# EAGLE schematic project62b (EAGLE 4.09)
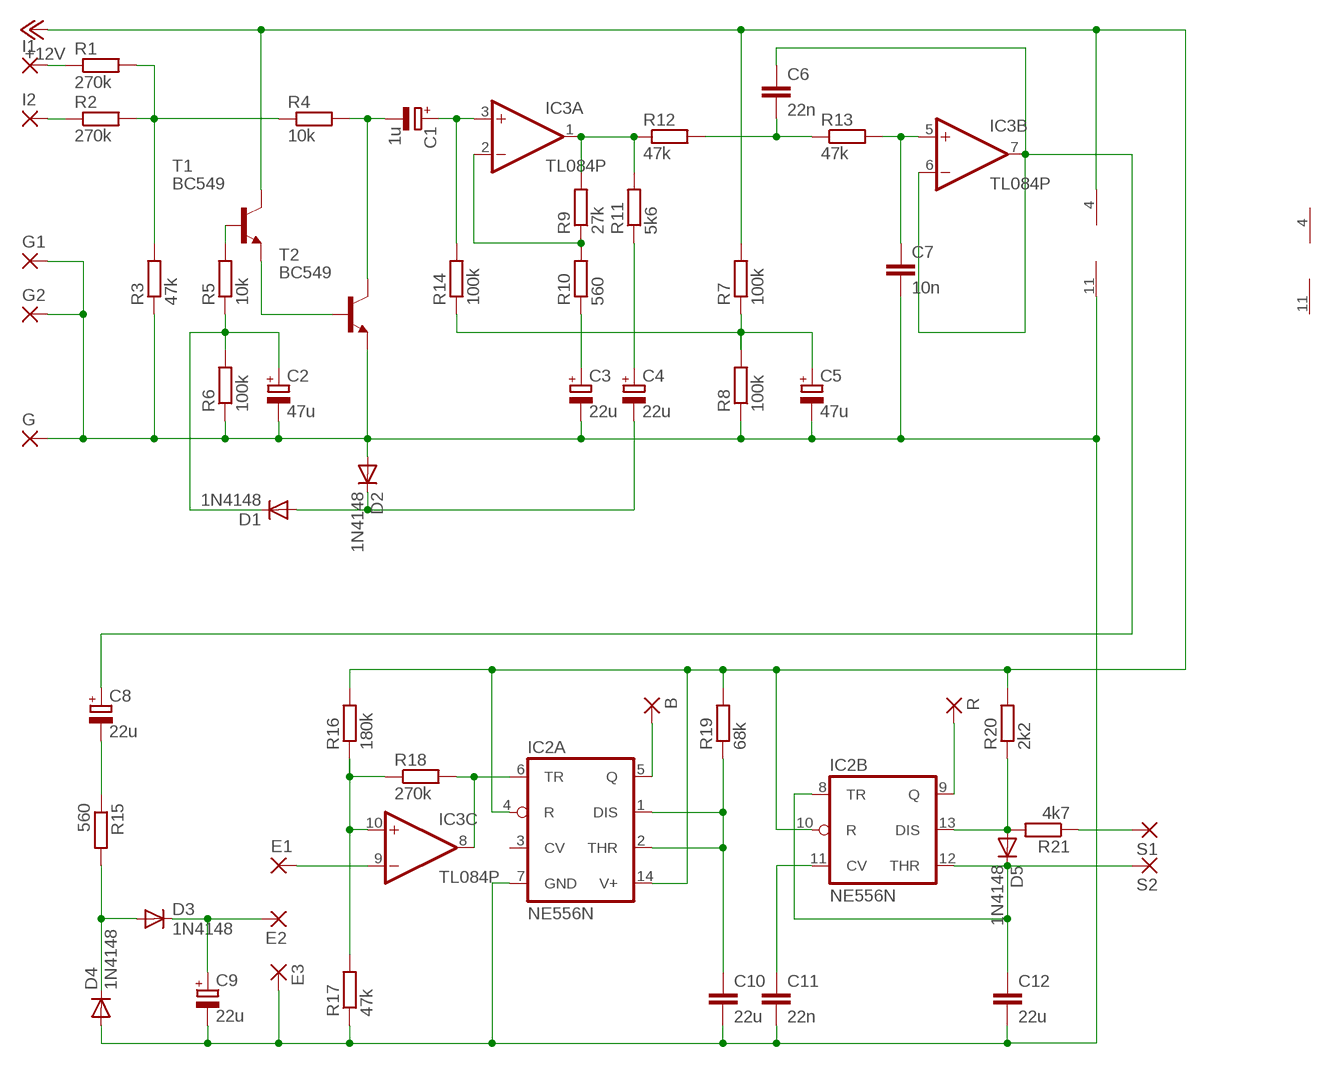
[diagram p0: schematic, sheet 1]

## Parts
B  2,54/0,8  [2,54/0,8]
C1  1u  CPOL-EUE5-6  [E5-6]
C2  47u  CPOL-EUE5-6  [E5-6]
C3  22u  CPOL-EUE5-6  [E5-6]
C4  22u  CPOL-EUE5-6  [E5-6]
C5  47u  CPOL-EUE5-6  [E5-6]
C6  22n  C-EU075-032X103  [C075-032X103]
C7  10n  C-EU075-032X103  [C075-032X103]
C8  22u  CPOL-EUE5-6  [E5-6]
C9  22u  CPOL-EUE5-6  [E5-6]
C10  22u  C-EU075-032X103  [C075-032X103]
C11  22n  C-EU075-032X103  [C075-032X103]
C12  22u  C-EU075-032X103  [C075-032X103]
D1  1N4148  [DO35-10]
D2  1N4148  [DO35-10]
D3  1N4148  [DO35-10]
D4  1N4148  [DO35-10]
D5  1N4148  [DO35-10]
E1  2,54/0,8  [2,54/0,8]
E2  2,54/0,8  [2,54/0,8]
E3  2,54/0,8  [2,54/0,8]
G  2,54/0,8  [2,54/0,8]
G1  2,54/0,8  [2,54/0,8]
G2  2,54/0,8  [2,54/0,8]
I1  2,54/0,8  [2,54/0,8]
I2  2,54/0,8  [2,54/0,8]
IC1  TL084_  [DIL14]
IC2  NE556N  [DIL14]
IC3  TL084P  [DIL14]
R  2,54/0,8  [2,54/0,8]
R1  270k  R-EU_0309/12  [0309/12]
R2  270k  R-EU_0309/12  [0309/12]
R3  47k  R-EU_0309/12  [0309/12]
R4  10k  R-EU_0309/12  [0309/12]
R5  10k  R-EU_0309/12  [0309/12]
R6  100k  R-EU_0309/12  [0309/12]
R7  100k  R-EU_0309/12  [0309/12]
R8  100k  R-EU_0309/12  [0309/12]
R9  27k  R-EU_0309/12  [0309/12]
R10  560  R-EU_0309/12  [0309/12]
R11  5k6  R-EU_0309/12  [0309/12]
R12  47k  R-EU_0309/12  [0309/12]
R13  47k  R-EU_0309/12  [0309/12]
R14  100k  R-EU_0309/12  [0309/12]
R15  560  R-EU_0309/12  [0309/12]
R16  180k  R-EU_0309/12  [0309/12]
R17  47k  R-EU_0309/12  [0309/12]
R18  270k  R-EU_0309/12  [0309/12]
R19  68k  R-EU_0309/12  [0309/12]
R20  2k2  R-EU_0309/12  [0309/12]
R21  4k7  R-EU_0309/12  [0309/12]
S1  2,54/0,8  [2,54/0,8]
S2  2,54/0,8  [2,54/0,8]
T1  BC549  BC547  [TO92]
T2  BC549  BC547  [TO92]

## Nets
+12V: IC1.4(P:V+) IC2.4(A:R) IC2.10(B:R) IC2.14(A:V+) R7.2 R16.2 R19.2 R20.2 T1.3(C)
GND_: C2.- C3.- C5.- C7.2 C9.- C10.2 C11.2 C12.2 D2.A D4.A E3.1(P) G1.1(P) G2.1(P) G.1(P) IC1.11(P:V-) IC2.7(A:GND) R3.1 R6.1 R8.1 R17.1 T2.1(E)
N$2: B.1(P) IC2.5(A:Q)
N$3: C6.1 C8.+ IC3.6(B:-IN) IC3.7(B:OUT)
N$4: R1.2 R2.2 R3.2 R4.1
N$5: T1.1(E) T2.2(B)
N$6: C1.- R4.2 T2.3(C)
N$7: C1.+ IC3.3(A:+IN) R14.2
N$8: I1.1(P) R1.1
N$9: R21.1 S1.1(P)
N$10: R5.2 T1.2(B)
N$11: C8.- R15.1
N$12: I2.1(P) R2.1
N$13: C5.+ R7.1 R8.2 R14.1
N$14: C6.2 R12.2 R13.1
N$15: D3.A D4.C R15.2
N$16: C7.1 IC3.5(B:+IN) R13.2
N$17: C4.- D1.A D2.C
N$18: IC3.1(A:OUT) R9.2 R11.2 R12.1
N$19: IC3.2(A:-IN) R9.1 R10.2
N$20: C3.+ R10.1
N$22: C4.+ R11.1
N$23: C9.+ D3.C E2.1(P)
N$24: D5.A IC2.13(B:DIS) R20.1 R21.2
N$25: E1.1(P) IC3.9(C:-IN)
N$27: IC3.10(C:+IN) R16.1 R17.2 R18.1
N$28: C12.1 D5.C IC2.8(B:TR) IC2.12(B:THR) S2.1(P)
N$29: C2.+ D1.C R5.1 R6.2
N$30: IC2.6(A:TR) IC3.8(C:OUT) R18.2
N$31: C11.1 IC2.11(B:CV)
N$34: C10.1 IC2.1(A:DIS) IC2.2(A:THR) R19.1
N$35: IC2.9(B:Q) R.1(P)
Unconnected: IC1.1(A:OUT) IC1.2(A:-IN) IC1.3(A:+IN) IC1.5(B:+IN) IC1.6(B:-IN) IC1.7(B:OUT) IC1.8(C:OUT) IC1.9(C:-IN) IC1.10(C:+IN) IC1.12(D:+IN) IC1.13(D:-IN) IC1.14(D:OUT) IC2.3(A:CV) IC3.12(D:+IN) IC3.13(D:-IN) IC3.14(D:OUT)

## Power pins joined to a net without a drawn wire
V+: IC3.4(P:V+)
V-: IC3.11(P:V-)

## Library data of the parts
B E1-E3 G G1 G2 I1 I2 R S1 S2 = wirepad:2,54/0,8: THROUGH-HOLE PAD
C1-C5 C8 C9 = rcl:CPOL-EU: POLARIZED CAPACITOR, European symbol
C6 C7 C10-C12 = rcl:C-EU: CAPACITOR, European symbol
D1-D5 = diode:1N4148: DIODE
IC1 = linear:TL084_
IC2 = linear:*556: Dual TIMER
IC3 = linear:TL084: OP AMP
R1-R21 = rcl:R-EU_: RESISTOR, European symbol
T1 T2 = transistor-npn:BC547: NPN TRANSISTOR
